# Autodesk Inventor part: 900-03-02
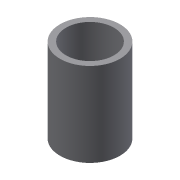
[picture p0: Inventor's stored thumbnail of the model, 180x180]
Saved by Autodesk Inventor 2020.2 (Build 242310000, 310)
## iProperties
Created: 2015-10
Part Number: 900-03-02
Material: Ogólny
Document SubType Name: Modeling
Designer: F.Stasiak
Density: 1 g/cm^3
Appearance: Domyślna
Catalog Web Link: www.expertbooks.pl
Manager: www.cadconsulting.pl
Company: Fabian Stasiak CAD Consulting
Author: F.Stasiak
Subject: Zbiór ćwiczeń. Autodesk Inventor 2020. Kurs Professional
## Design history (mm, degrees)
sketch "Szkic1"
  geometry: C1 r 20 at (0, 0); C2 r 25 at (0, 0); 1 further point
  constraints: 2 centre point, 2 coincident
  dimensions: "d0" = 40 diameter of C1; "d1" = 50 diameter of C2
extrude "Wyciągnięcie proste1" new body sketch "Szkic1" stored distance "d2" = 70; taper "d3" = 0 deg
node "Bryła1"
